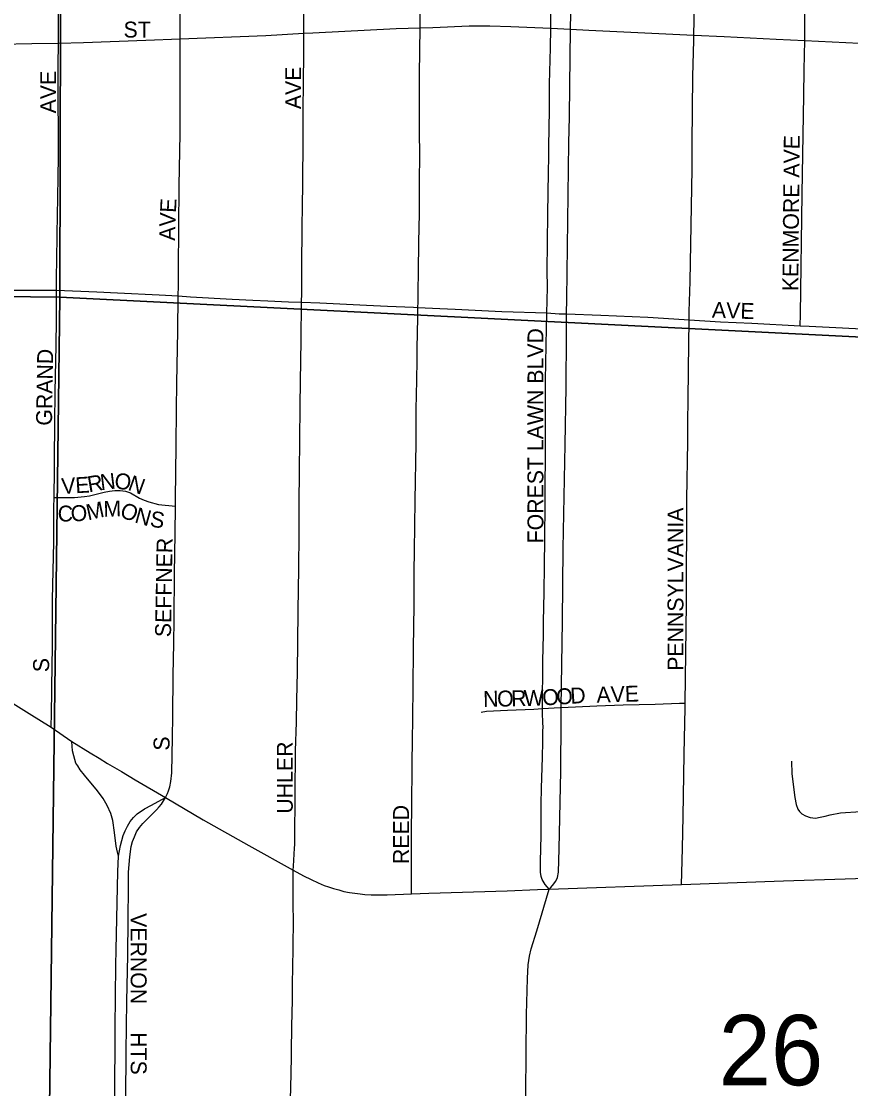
# Model space of a CAD drawing. Extents: x -97 to 34, y -21 to 22.
# Drawn here: x 6.585 to 7.079, y 18.991 to 19.626 of the extents above; entities that cross this region are included whole.
import ezdxf

# ---------------------------------------------------------------- set-up
doc = ezdxf.new("R2010")
doc.units = 0
for name, color, linetype in [('GM_X_City_Street', 7, 'Continuous'), ('GM_X_City_Street_Text', 7, 'Continuous'), ('GM_X_Section', 7, 'Continuous'), ('GM_X_Section_Text', 7, 'Continuous'), ('GM_X_State_Route', 7, 'Continuous')]:
    doc.layers.add(name, color=color, linetype=linetype)

msp = doc.modelspace()

# ---------------------------------------------------------------- linework, layer by layer
at = {"layer": 'GM_X_City_Street'}
for points in [[(6.98549, 19.61802), (6.98608, 19.64487), (6.98646, 19.66758), (6.98682, 19.69228), (6.98688, 19.70759), (6.98687, 19.71913), (6.98686, 19.72592)], [(7.05138, 19.61479), (7.0514, 19.61595), (7.05142, 19.62427), (7.05174, 19.6427), (7.05253, 19.69195), (7.05301, 19.72206), (7.05312, 19.72904)], [(6.82244, 19.62241), (6.82252, 19.6312), (6.82267, 19.65012), (6.82284, 19.67021), (6.82287, 19.7013), (6.82287, 19.71061), (6.82287, 19.71873)], [(6.90029, 19.62209), (6.90058, 19.64137), (6.90118, 19.67546), (6.901, 19.71471), (6.90097, 19.72216)], [(6.91208, 19.62153), (6.91232, 19.64052), (6.91274, 19.66219), (6.91284, 19.68076), (6.91313, 19.7037), (6.91327, 19.71478), (6.91337, 19.7227)], [(6.67968, 19.61584), (6.67975, 19.63171), (6.67981, 19.64667), (6.67988, 19.66222)], [(6.75324, 19.61917), (6.75324, 19.62486), (6.7533, 19.62795), (6.75332, 19.63105), (6.75329, 19.64343), (6.75324, 19.66572)], [(6.60722, 19.61329), (6.60729, 19.62212), (6.60743, 19.63955), (6.60751, 19.65073), (6.60758, 19.65859), (6.60759, 19.65914)], [(6.82244, 19.62241), (6.83005, 19.62263), (6.85172, 19.62347), (6.8577, 19.62357), (6.86405, 19.62358), (6.87644, 19.62321), (6.90029, 19.62209)], [(6.67968, 19.61584), (6.73075, 19.61786), (6.75324, 19.61917)], [(6.75198, 19.45913), (6.75205, 19.46454), (6.75219, 19.48361), (6.75233, 19.50038), (6.75247, 19.51978), (6.75268, 19.52589), (6.75289, 19.55941), (6.75295, 19.5691), (6.7532, 19.59379), (6.7533, 19.60318), (6.75324, 19.61867), (6.75324, 19.61917)], [(6.75324, 19.61917), (6.75866, 19.61945), (6.80832, 19.62195), (6.82244, 19.62241)], [(6.82121, 19.45596), (6.82128, 19.4591), (6.82138, 19.46571), (6.82156, 19.47721), (6.82182, 19.49482), (6.82208, 19.51191), (6.82222, 19.53484), (6.82227, 19.54277), (6.82221, 19.56452), (6.8222, 19.5947), (6.82244, 19.62241)], [(6.89794, 19.45277), (6.89803, 19.46001), (6.89823, 19.46819), (6.8982, 19.47747), (6.89842, 19.5116), (6.89883, 19.53639), (6.89907, 19.54566), (6.89904, 19.55182), (6.89948, 19.57351), (6.89951, 19.5859), (6.8996, 19.58894), (6.90012, 19.61044), (6.90029, 19.62209)], [(6.90029, 19.62209), (6.91208, 19.62153)], [(6.90969, 19.4521), (6.90973, 19.46108), (6.91109, 19.55393), (6.91142, 19.56938), (6.91165, 19.58794), (6.91208, 19.62153)], [(6.91208, 19.62153), (6.92287, 19.62099), (6.98549, 19.61802)], [(6.98259, 19.44866), (6.98271, 19.4535), (6.98317, 19.47134), (6.98444, 19.53838), (6.98443, 19.55357), (6.98478, 19.59363), (6.98543, 19.61483), (6.98549, 19.61802)], [(6.98549, 19.61802), (7.00346, 19.61713), (7.03438, 19.61555), (7.05138, 19.61479)], [(6.53544, 19.61084), (6.54189, 19.61116), (6.55093, 19.61175), (6.5569, 19.61205), (6.57239, 19.61256), (6.59134, 19.61297), (6.60722, 19.61329)], [(6.60609, 19.46623), (6.60618, 19.47363), (6.60631, 19.48465), (6.60648, 19.49863), (6.60671, 19.51178), (6.60685, 19.52033), (6.60709, 19.53463), (6.60726, 19.5445), (6.60721, 19.56424), (6.60719, 19.57558), (6.60715, 19.58907), (6.60712, 19.59997), (6.60722, 19.61329)], [(6.60722, 19.61329), (6.62213, 19.61354), (6.65935, 19.61501), (6.67968, 19.61584)], [(6.67855, 19.4628), (6.67864, 19.46892), (6.67878, 19.47922), (6.67882, 19.50329), (6.67916, 19.52827), (6.67977, 19.55948), (6.67967, 19.61249), (6.67968, 19.61584)], [(7.04872, 19.4451), (7.04881, 19.45174), (7.04979, 19.52352), (7.05094, 19.58203), (7.0511, 19.59729), (7.05138, 19.61479)], [(7.05138, 19.61479), (7.08395, 19.61326), (7.10137, 19.61249), (7.11496, 19.61231), (7.11693, 19.61227)], [(6.53432, 19.46641), (6.53719, 19.46635), (6.58061, 19.46629), (6.59301, 19.46631), (6.60538, 19.46627), (6.60609, 19.46623)], [(6.60464, 19.34292), (6.60493, 19.35941), (6.60494, 19.3656), (6.60513, 19.38712), (6.60536, 19.40569), (6.60596, 19.43342), (6.6061, 19.44864), (6.60612, 19.46295), (6.60609, 19.46623)], [(6.60609, 19.46623), (6.63012, 19.46526), (6.6425, 19.46471), (6.66726, 19.46351), (6.67855, 19.4628)], [(6.67696, 19.33773), (6.677, 19.34203), (6.67734, 19.37365), (6.67748, 19.3954), (6.67764, 19.41095), (6.67826, 19.44199), (6.67855, 19.4628)], [(6.67855, 19.4628), (6.68587, 19.46234), (6.71064, 19.46087), (6.72285, 19.46031), (6.73194, 19.45987), (6.74425, 19.45941), (6.75198, 19.45913)], [(6.74698, 19.12122), (6.74711, 19.1236), (6.74771, 19.13418), (6.74786, 19.13634), (6.74789, 19.13981), (6.74844, 19.19207), (6.74888, 19.20917), (6.74914, 19.2225), (6.74946, 19.23894), (6.75001, 19.27516), (6.75022, 19.28876), (6.75039, 19.3001), (6.75049, 19.32181), (6.7506, 19.33908), (6.75072, 19.35876), (6.75094, 19.37656), (6.75121, 19.39761), (6.75138, 19.41175), (6.75169, 19.43643), (6.75198, 19.45913)], [(6.75198, 19.45913), (6.76283, 19.45873), (6.79068, 19.45733), (6.80311, 19.45665), (6.81864, 19.45606), (6.82121, 19.45596)], [(6.81738, 19.10703), (6.81739, 19.11372), (6.81741, 19.12523), (6.81743, 19.13494), (6.81744, 19.14678), (6.81756, 19.1568), (6.81787, 19.18585), (6.81799, 19.19742), (6.81815, 19.21222), (6.81835, 19.22965), (6.8186, 19.253), (6.81888, 19.27882), (6.81901, 19.29838), (6.81916, 19.31138), (6.81933, 19.32601), (6.8195, 19.34115), (6.82014, 19.37522), (6.82008, 19.38764), (6.8202, 19.39524), (6.82048, 19.41267), (6.82067, 19.42467), (6.82078, 19.43157), (6.82107, 19.44993), (6.82121, 19.45596)], [(6.82121, 19.45596), (6.83414, 19.45543), (6.84337, 19.45487), (6.87113, 19.45358), (6.89794, 19.45277)], [(6.8953, 19.21731), (6.89538, 19.22618), (6.89548, 19.23654), (6.89548, 19.24581), (6.89603, 19.26118), (6.89603, 19.26909), (6.89625, 19.28637), (6.89645, 19.30263), (6.89664, 19.31793), (6.89669, 19.32188), (6.89687, 19.33541), (6.89695, 19.34852), (6.89709, 19.36858), (6.89715, 19.37873), (6.89716, 19.39604), (6.89717, 19.40344), (6.89719, 19.41271), (6.89779, 19.44371), (6.89794, 19.45277)], [(6.89794, 19.45277), (6.90527, 19.45227), (6.90969, 19.4521)], [(6.90642, 19.21796), (6.90727, 19.26927), (6.90757, 19.31261), (6.90875, 19.37453), (6.90941, 19.4085), (6.90964, 19.43942), (6.90969, 19.4521)], [(6.90969, 19.4521), (6.9301, 19.45137), (6.95793, 19.45016), (6.9796, 19.44885), (6.98259, 19.44866)], [(6.98023, 19.22054), (6.98098, 19.27975), (6.98129, 19.34186), (6.98175, 19.37599), (6.98189, 19.38832), (6.98198, 19.40058), (6.98224, 19.41911), (6.98259, 19.44866)], [(6.98259, 19.44866), (7.00126, 19.44746), (7.01984, 19.44661), (7.04872, 19.4451)], [(7.04872, 19.4451), (7.05396, 19.44483), (7.09741, 19.4426), (7.11562, 19.44157)], [(6.60464, 19.34292), (6.60971, 19.34295), (6.61675, 19.34299), (6.62273, 19.34343), (6.62569, 19.34387), (6.63456, 19.34607), (6.63763, 19.34663), (6.64074, 19.34697), (6.6439, 19.34706), (6.64709, 19.34666), (6.65017, 19.34568), (6.65557, 19.34259), (6.65819, 19.34129), (6.66096, 19.34028), (6.66674, 19.3388), (6.67696, 19.33773)], [(6.60287, 19.20615), (6.60307, 19.2146), (6.60336, 19.22756), (6.6034, 19.23026), (6.60379, 19.25437), (6.60374, 19.26673), (6.60382, 19.28219), (6.60443, 19.31623), (6.60459, 19.33703), (6.60464, 19.34292)], [(6.67101, 19.1644), (6.67225, 19.16668), (6.67281, 19.16834), (6.67365, 19.17082), (6.6741, 19.17396), (6.67465, 19.17902), (6.67519, 19.20007), (6.6753, 19.21273), (6.67553, 19.23723), (6.67586, 19.25599), (6.67611, 19.27029), (6.67641, 19.29774), (6.67665, 19.32134), (6.67696, 19.33773)], [(6.8589, 19.21526), (6.862, 19.2157), (6.87452, 19.21638), (6.89016, 19.217), (6.8953, 19.21731)], [(6.89936, 19.10983), (6.89698, 19.11269), (6.89519, 19.11554), (6.8945, 19.1173), (6.89412, 19.11995), (6.89423, 19.1264), (6.89461, 19.14187), (6.89454, 19.15399), (6.89451, 19.16041), (6.89477, 19.16993), (6.89527, 19.18833), (6.89556, 19.19761), (6.89563, 19.20389), (6.89564, 19.20651), (6.89558, 19.20856), (6.89532, 19.21488), (6.8953, 19.21731)], [(6.8953, 19.21731), (6.90581, 19.21793), (6.90642, 19.21796)], [(6.89936, 19.10983), (6.90002, 19.11059), (6.90131, 19.11205), (6.90336, 19.11471), (6.90424, 19.11676), (6.90483, 19.11995), (6.90516, 19.13386), (6.90626, 19.18005), (6.90639, 19.21084), (6.90642, 19.21796)], [(6.90642, 19.21796), (6.92773, 19.21888), (6.94339, 19.21944), (6.96245, 19.22001), (6.97693, 19.22044), (6.98023, 19.22054)], [(6.97809, 19.11263), (6.97829, 19.11957), (6.9787, 19.13427), (6.97912, 19.15309), (6.97962, 19.19025), (6.98019, 19.21769), (6.98023, 19.22054)], [(6.64305, 19.12953), (6.64231, 19.13178), (6.64196, 19.13363), (6.6416, 19.13553), (6.64067, 19.14362), (6.63973, 19.15074), (6.63836, 19.15495), (6.63626, 19.15965), (6.63378, 19.16386), (6.63056, 19.16843), (6.62276, 19.17771), (6.62023, 19.18081), (6.61873, 19.18319), (6.61769, 19.18484), (6.61638, 19.18915), (6.61569, 19.19209), (6.61541, 19.19498), (6.61533, 19.19779)], [(7.04354, 19.18608), (7.04371, 19.17852), (7.04552, 19.16442), (7.04633, 19.16028), (7.04731, 19.15744), (7.04824, 19.15613), (7.04961, 19.15465), (7.05176, 19.15352), (7.05467, 19.15252), (7.05772, 19.15218), (7.06068, 19.1526), (7.0636, 19.15337), (7.06655, 19.15416), (7.07259, 19.15529), (7.08485, 19.15608), (7.10295, 19.15692), (7.11161, 19.15738)], [(6.64305, 19.12953), (6.64414, 19.13578), (6.64489, 19.13879), (6.64584, 19.14174), (6.64698, 19.14463), (6.64833, 19.14742), (6.64997, 19.15004), (6.65191, 19.15245), (6.65412, 19.15464), (6.65855, 19.15756), (6.66267, 19.15983), (6.67101, 19.1644)], [(6.6468, 18.94164), (6.64685, 18.94792), (6.64705, 18.96333), (6.64738, 18.98501), (6.64766, 19.01316), (6.64784, 19.02818), (6.64805, 19.04322), (6.64861, 19.07034), (6.6488, 19.09203), (6.64888, 19.11059), (6.64897, 19.11996), (6.64967, 19.12918), (6.65064, 19.13526), (6.65141, 19.13821), (6.65245, 19.14109), (6.65378, 19.14389), (6.65546, 19.1465), (6.65745, 19.14889), (6.65947, 19.15088), (6.66566, 19.15701), (6.66722, 19.1589), (6.6685, 19.16045), (6.67101, 19.1644)], [(6.64027, 18.94164), (6.64029, 18.94684), (6.64083, 18.98398), (6.64101, 19.02738), (6.64145, 19.06456), (6.64168, 19.07384), (6.64191, 19.08313), (6.64266, 19.12035), (6.64305, 19.12953)], [(6.74664, 18.94016), (6.74645, 18.94121), (6.74566, 18.94486), (6.74551, 18.94902), (6.74548, 18.95198), (6.74553, 18.96406), (6.74555, 18.96995), (6.74548, 18.97295), (6.74542, 18.98222), (6.74559, 18.99464), (6.74568, 18.99753), (6.74608, 19.02824), (6.74665, 19.04373), (6.74658, 19.05304), (6.74676, 19.06376), (6.74686, 19.07419), (6.74716, 19.09287), (6.74703, 19.09882), (6.74702, 19.1018), (6.74702, 19.10447), (6.74698, 19.12122)], [(6.88464, 18.93896), (6.8849, 18.95981), (6.88539, 18.98852), (6.88575, 19.0353), (6.88637, 19.05671), (6.88673, 19.06475), (6.8876, 19.06996), (6.88859, 19.07429), (6.8919, 19.08514), (6.89936, 19.10983)]]:
    msp.add_lwpolyline(points, dxfattribs=at)
at = {"layer": 'GM_X_Section'}
for points in [[(5.59805, 20.47457), (6.61045, 20.46615), (6.60805, 19.46219), (5.59615, 19.47364)], [(7.61995, 20.4372), (7.61097, 19.41205), (6.60805, 19.46219), (6.61045, 20.46615)], [(5.59615, 19.47364), (6.60805, 19.46219), (6.59547, 18.46625), (5.59082, 18.47236)], [(6.60805, 19.46219), (7.61097, 19.41205), (7.59861, 18.45475), (6.59547, 18.46625)]]:
    msp.add_lwpolyline(points, close=True, dxfattribs=at)
at = {"layer": 'GM_X_State_Route'}
for points in [[(6.45623, 19.29904), (6.47079, 19.28975), (6.48923, 19.2782), (6.4944, 19.2748), (6.49708, 19.27304), (6.51432, 19.26177), (6.52583, 19.25399), (6.53257, 19.24962), (6.54717, 19.24032), (6.57155, 19.22576), (6.57871, 19.22128), (6.58978, 19.21434), (6.60287, 19.20615)], [(6.60287, 19.20615), (6.61533, 19.19779), (6.62611, 19.19105), (6.63146, 19.18772), (6.63655, 19.18466), (6.64483, 19.17983), (6.65298, 19.17499), (6.67101, 19.1644), (6.69344, 19.15113), (6.72049, 19.13579), (6.74698, 19.12122), (6.75319, 19.11781), (6.75768, 19.11554), (6.76186, 19.11358), (6.76532, 19.1121), (6.7679, 19.11124), (6.77105, 19.1102), (6.7741, 19.10936), (6.77716, 19.10854), (6.78045, 19.10795), (6.78365, 19.1074), (6.78684, 19.10702), (6.78951, 19.10677), (6.79328, 19.10652), (6.80283, 19.10646), (6.81738, 19.10703), (6.82775, 19.10744), (6.87425, 19.10893), (6.89236, 19.10958)], [(6.89236, 19.10958), (6.89936, 19.10983), (6.97809, 19.11263), (7.03869, 19.11478), (7.11208, 19.11727), (7.13801, 19.1181), (7.18551, 19.11967), (7.22178, 19.12086), (7.2612, 19.12232), (7.28074, 19.12305), (7.31482, 19.12415), (7.3524, 19.12513), (7.35669, 19.1252)]]:
    msp.add_lwpolyline(points, dxfattribs=at)

# ---------------------------------------------------------------- texts
at = {"layer": 'GM_X_City_Street_Text'}
for s, height, rotation, p in [('ST', 0.00947, 0.00001, (6.64599, 19.61656)), ('AVE', 0.00947, 90, (6.75171, 19.57394)), ('AVE', 0.00947, 90, (6.60587, 19.57144)), ('KENMORE AVE', 0.0094697, 89.43302, (7.04754, 19.46563)), ('E', 0.00947, 87.15804, (6.67716, 19.51215)), ('V', 0.00947, 87.50759, (6.6768, 19.50383)), ('A', 0.00947, 89.36607, (6.67671, 19.49558)), ('AVE', 0.00947, 358.02636, (6.99605, 19.44989)), ('FOREST LAWN BLVD', 0.0094697, 90, (6.89587, 19.31561)), ('GRAND', 0.00947, 89.02815, (6.60338, 19.38557)), ('N', 0.00947, 6.92438, (6.63263, 19.34717)), ('O', 0.00947, 354.90056, (6.64037, 19.34816)), ('V', 0.00947, 3.45501, (6.60926, 19.34489)), ('E', 0.00947, 3.44509, (6.61758, 19.3454)), ('R', 0.00947, 9.67663, (6.62535, 19.34592)), ('N', 0.00947, 339.94782, (6.64804, 19.34756)), ('C', 0.00947, 0.09715, (6.60683, 19.3286)), ('O', 0.00947, 2.56341, (6.61477, 19.32863)), ('M', 0.00947, 12.59039, (6.62489, 19.32924)), ('M', 0.00947, 1.62149, (6.63418, 19.33136)), ('O', 0.00947, 337.00519, (6.64312, 19.33184)), ('N', 0.00947, 344.62359, (6.65209, 19.32813)), ('S', 0.00947, 351.48737, (6.66134, 19.32566)), ('PENNSYLVANIA', 0.0094697, 90, (6.97921, 19.23978)), ('SEFFNER', 0.00947, 89.03135, (6.67421, 19.25974)), ('S', 0.00947, 90, (6.60171, 19.23895)), ('O', 0.00947, 3.5684, (6.90382, 19.21961)), ('D', 0.00947, 3.56542, (6.91214, 19.22012)), ('AVE', 0.00947, 1.90818, (6.9276, 19.22072)), ('N', 0.00947, 1.37693, (6.86012, 19.21823)), ('O', 0.00947, 1.4012, (6.86845, 19.21843)), ('R', 0.00947, 1.38416, (6.87678, 19.21863)), ('W', 0.00947, 1.61234, (6.88432, 19.21881)), ('O', 0.00947, 3.23002, (6.89544, 19.21913)), ('S', 0.00947, 90, (6.67338, 19.19228)), ('UHLER', 0.00947, 90, (6.74671, 19.15478)), ('REED', 0.00947, 90, (6.81588, 19.12478)), ('VERNON', 0.00947, 270, (6.65027, 19.09561)), ('HTS', 0.00947, 270, (6.65027, 19.02478))]:
    msp.add_text(s, height=height, rotation=rotation, dxfattribs=at).set_placement(p)
at = {"layer": 'GM_X_Section_Text'}
msp.add_text('26', height=0.041856, rotation=0.00001, dxfattribs=at).set_placement((7.00016, 18.99317))

doc.saveas('drawing.dxf')
